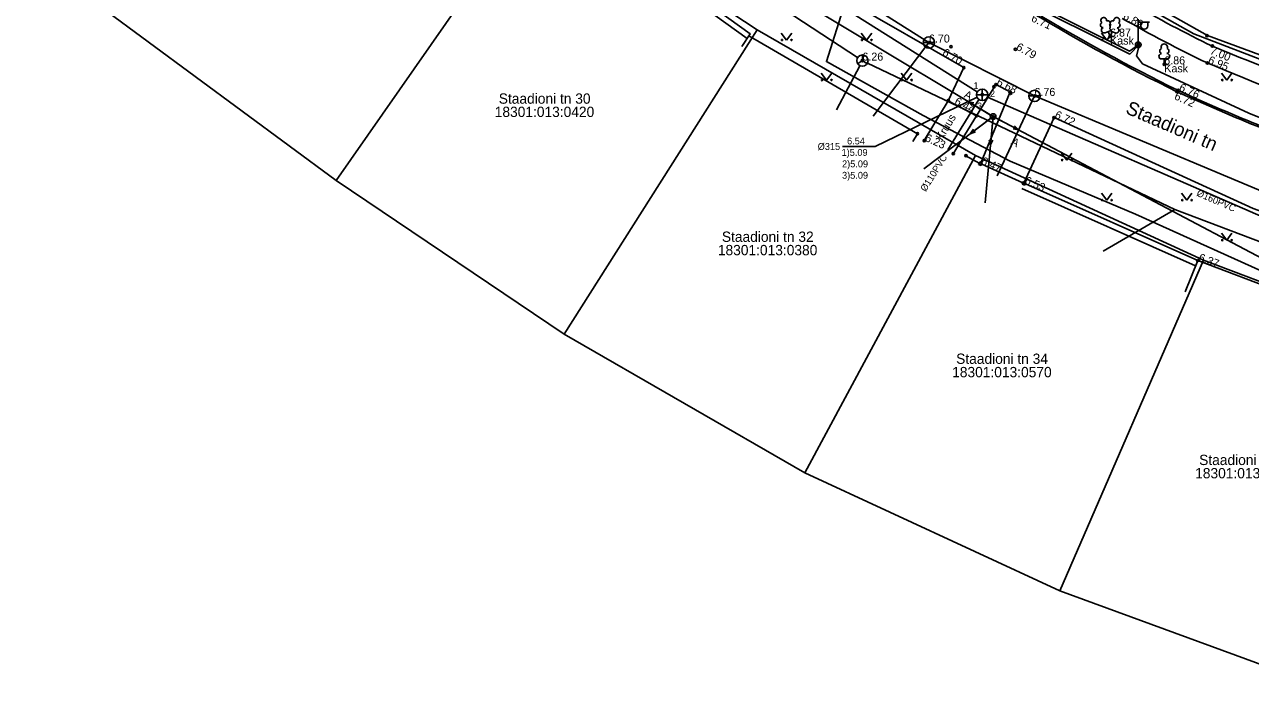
# Model space of a CAD drawing. Extents: x 473307 to 473719, y 6532843 to 6533381.
# Drawn here: x 473476.8 to 473584, y 6532884.7 to 6532942.8 of the extents above; entities that cross this region are included whole.
import ezdxf

# ---------------------------------------------------------------- set-up
doc = ezdxf.new("R2010")
doc.units = 0
for name, color, linetype in [('AED', 7, 'Continuous'), ('Default', 7, 'Continuous'), ('HALJASTUS', 7, 'Continuous'), ('KKAEV', 7, 'Continuous'), ('KKAEV_NR', 7, 'Continuous'), ('KORGUS', 7, 'Continuous'), ('KPKAABEL', 7, 'Continuous'), ('KTRASS', 7, 'Continuous'), ('KTRASS_TEKST', 7, 'Continuous'), ('MPKAABEL', 7, 'Continuous'), ('MPOHULIIN', 7, 'Continuous'), ('PIIR', 7, 'Continuous'), ('POST', 7, 'Continuous'), ('PUU', 7, 'Continuous'), ('SIKAEV', 7, 'Continuous'), ('SITRASS', 7, 'Continuous'), ('TEE', 7, 'Continuous'), ('VKAEV', 7, 'Continuous'), ('VTRASS', 7, 'Continuous')]:
    doc.layers.add(name, color=color, linetype=linetype)

# ---------------------------------------------------------------- blocks, each defined once
blk = doc.blocks.new('KAKAEV')
at = {"layer": 'Default'}
for p, q in [((-1, 0), (1, 0)), ((0, -1), (0, 1))]:
    blk.add_line(p, q, dxfattribs=at)
blk.add_circle((0, 0), 1, dxfattribs=at)
blk = doc.blocks.new('SIKAEV')
at = {"layer": 'Default'}
for p, q in [((0, 0), (-0.83, -0.55)), ((0, 1), (0, 0)), ((0, 0), (0.83, -0.55))]:
    blk.add_line(p, q, dxfattribs=at)
blk.add_circle((0, 0), 1, dxfattribs=at)
blk = doc.blocks.new('PUPOST')
at = {"layer": 'Default'}
blk.add_circle((0, 0), 0.5, dxfattribs=at)
blk = doc.blocks.new('VEKAEV')
at = {"layer": 'Default'}
blk.add_line((-1, 0), (1, 0), dxfattribs=at)
blk.add_circle((0, 0), 1, dxfattribs=at)
blk = doc.blocks.new('VARPOS')
at = {"layer": 'Default'}
for p, q in [((-0.25, 0.25), (-0.25, -0.25)), ((-0.25, 0.25), (0.25, 0.25)), ((0.25, 0.25), (0.25, -0.25)), ((-0.25, -0.25), (0.25, -0.25))]:
    blk.add_line(p, q, dxfattribs=at)
blk = doc.blocks.new('LEHTP1')
at = {"layer": 'Default'}
for p, q in [((0.48, 0.95), (-0.48, 0.95)), ((0, 0), (0, 0.95)), ((0.76, 0), (0, 0))]:
    blk.add_line(p, q, dxfattribs=at)
for centre, radius, start, end in [((-0.34, 2.35), 0.465, 109.0217, 253.1415), ((0, 3.04), 0.554, 332.5799, 207.4201), ((0.34, 2.35), 0.465, 286.8508, 70.9859), ((-0.47, 1.42), 0.475, 90.0016, 269.3953), ((0.47, 1.42), 0.475, 270.6047, 89.9984)]:
    blk.add_arc(centre, radius, start, end, dxfattribs=at)
blk = doc.blocks.new('MEPOST')
at = {"layer": 'Default'}
blk.add_circle((0, 0), 0.5, dxfattribs=at)
for start, end in [(0, 180), (180, 0)]:
    blk.add_arc((0, 0), 0.25, start, end, dxfattribs=at)
blk = doc.blocks.new('VAPOST')
at = {"layer": 'Default'}
for p, q in [((0, 0.5), (0, 4.5)), ((0, 4), (2, 4)), ((0.45, 3.36), (0.45, 4)), ((1.68, 3.36), (1.68, 4))]:
    blk.add_line(p, q, dxfattribs=at)
blk.add_arc((1.07, 3.36), 0.613, 180, 0, dxfattribs=at)
blk = doc.blocks.new('LEHTP2')
at = {"layer": 'Default'}
for p, q in [((-0.88, 0.67), (0.01, 1.02)), ((0, 0), (-0.35, 0.88)), ((0, 0), (0.36, 0.88)), ((0.76, 0), (0, 0)), ((0.01, 1.02), (0.89, 0.66))]:
    blk.add_line(p, q, dxfattribs=at)
blk.add_lwpolyline([(0.01, 2.01), (-0.03, 1.86), (-0.03, 1.82), (-0.01, 1.76), (0.03, 1.69), (0.04, 1.65), (0.01, 1.58), (-0.04, 1.48), (-0.05, 1.43), (-0.04, 1.4), (-0.02, 1.34), (0.05, 1.22), (0.06, 1.18), (0.05, 1.14), (0.02, 1.07), (0.01, 1.02)], dxfattribs=at)
for centre, radius, start, end in [((-1.26, 2.01), 0.448, 111.4304, 274.4987), ((-1.11, 2.83), 0.512, 111.5027, 232.5173), ((-1.11, 2.83), 0.512, 350.4856, 111.5002), ((-0.44, 2.33), 0.448, 308.5041, 111.5725), ((0.48, 2.32), 0.45, 67.7016, 230.5126), ((1.16, 2.81), 0.512, 67.6168, 188.6314), ((1.29, 1.99), 0.448, 264.6183, 67.6866), ((1.16, 2.81), 0.512, 306.5997, 67.6143), ((-1.05, 1.12), 0.475, 111.5014, 291.5004), ((0.01, 1.53), 0.475, 66.7655, 111.5015), ((1.07, 1.1), 0.475, 247.6166, 67.6155)]:
    blk.add_arc(centre, radius, start, end, dxfattribs=at)
blk = doc.blocks.new('MPSUUN')
at = {"layer": 'Default'}
for p, q in [((0.5, 0), (5, 0)), ((5, 0), (4.1, 0.3)), ((5, 0), (4.1, -0.3))]:
    blk.add_line(p, q, dxfattribs=at)
blk = doc.blocks.new('MURU')
at = {"layer": 'Default'}
for p, q in [((-0.93, 1.21), (0, 0)), ((0, 0), (0.89, 1.21))]:
    blk.add_line(p, q, dxfattribs=at)
for centre in [(-0.8, 0), (0.86, 0)]:
    blk.add_circle(centre, 0.11, dxfattribs=at)

msp = doc.modelspace()

# ---------------------------------------------------------------- linework, layer by layer
at = {"layer": 'AED'}
for points in [[(473550.05, 6532959.21), (473554.17, 6532956.45), (473573.72, 6532945.51), (473580.25, 6532941.8), (473591.86, 6532937.52), (473605.92, 6532932.3), (473608.29, 6532931.42), (473621.23, 6532928.23), (473637.54, 6532925.08), (473652.53, 6532925.14), (473654.3, 6532926.84), (473651.93, 6532941.68), (473648.98, 6532959.55), (473630.65, 6532956.49)], [(473528.46, 6532950.46), (473540.26, 6532941.94), (473539.54, 6532940.84)], [(473559.12, 6532931.28), (473560.28, 6532930.64)], [(473560.51, 6532930.53), (473564.09, 6532928.92)], [(473564.32, 6532928.82), (473579.4, 6532922.12)], [(473596.07, 6532915.79), (473579.4, 6532922.12), (473578.3, 6532919.39)]]:
    msp.add_lwpolyline(points, dxfattribs=at)
at = {"layer": 'HALJASTUS'}
for points in [[(473528.06, 6532950.13), (473539.99, 6532941.52)], [(473540.15, 6532941.77), (473554.89, 6532933.2), (473554.49, 6532932.53)], [(473564, 6532928.41), (473579.2, 6532921.66)]]:
    msp.add_lwpolyline(points, dxfattribs=at)
at = {"layer": 'KKAEV_NR'}
msp.add_lwpolyline([(473560.1, 6532936.39), (473551.19, 6532932.09), (473548.34, 6532932.09)], dxfattribs=at)
at = {"layer": 'KORGUS'}
for centre in [(473555.89, 6532941.18), (473571.73, 6532941.7), (473580.2, 6532941.77), (473557.82, 6532940.82), (473557.82, 6532940.82), (473563.45, 6532940.59), (473563.45, 6532940.59), (473580.68, 6532940.87), (473550.07, 6532939.6), (473550.07, 6532939.6), (473558.94, 6532938.99), (473576.47, 6532939.27), (473580.24, 6532939.4), (473560.55, 6532936.61), (473560.55, 6532936.61), (473560.55, 6532936.61), (473560.55, 6532936.61), (473561.58, 6532937.32), (473561.58, 6532937.32), (473561.74, 6532937.5), (473562.98, 6532936.86), (473563.03, 6532936.73), (473577.58, 6532936.88), (473577.7, 6532937.01), (473557.58, 6532936.09), (473565.12, 6532936.51), (473560.06, 6532934.77), (473561.5, 6532934.71), (473566.83, 6532934.62), (473554.89, 6532933.2), (473555.48, 6532932.6), (473558.02, 6532931.46), (473559.12, 6532931.28), (473560.39, 6532930.58), (473564.2, 6532928.87), (473579.4, 6532922.12)]:
    msp.add_circle(centre, 0.1, dxfattribs=at)
at = {"layer": 'KPKAABEL'}
msp.add_lwpolyline([(473552.43, 6532965.74), (473552.25, 6532955.74), (473551.4, 6532952.25), (473548.54, 6532944.6), (473546.92, 6532939.52), (473555.37, 6532934.8), (473562.98, 6532930.8), (473573.94, 6532926.16), (473585, 6532921.18), (473597.71, 6532916.33), (473608.1, 6532913.36), (473620.13, 6532910.12), (473635.44, 6532908.14), (473647.32, 6532907.13), (473658.18, 6532907.68), (473669.9, 6532907.95), (473678.24, 6532908.17), (473679.84, 6532908.72), (473681.3, 6532908.76), (473682.62, 6532907.44), (473683.14, 6532903.8)], dxfattribs=at)
at = {"layer": 'KTRASS'}
for p, q in [((473505.34, 6532971.33), (473560.12, 6532936.88)), ((473557.55, 6532931.79), (473560.26, 6532936.2)), ((473561.01, 6532936.41), (473600.98, 6532918.97))]:
    msp.add_line(p, q, dxfattribs=at)
at = {"layer": 'MPKAABEL'}
for points in [[(473592.16, 6532931.66), (473583.87, 6532934.99), (473574.57, 6532939.31), (473574.03, 6532940.03), (473574.3, 6532941.03), (473573.47, 6532940.17), (473563.47, 6532945.17), (473556.13, 6532949.37), (473546.42, 6532955.03), (473536.14, 6532961.46), (473535.98, 6532962.87), (473534.66, 6532962.57), (473525.66, 6532968.57), (473517.1, 6532975.07), (473509.15, 6532981.52), (473503.05, 6532987.78), (473502.69, 6532988.63), (473501.29, 6532988.87), (473494.53, 6532995.72), (473488.46, 6533001.87), (473481.1, 6533010.08), (473475.3, 6533017.48)], [(473535.98, 6532962.87), (473536.14, 6532961.46), (473546.42, 6532955.03), (473556.13, 6532949.37), (473563.47, 6532945.17), (473573.47, 6532940.17), (473574.3, 6532941.03)], [(473574.3, 6532941.03), (473573.43, 6532940.43), (473563.57, 6532945.36), (473556.23, 6532949.55)], [(473574.3, 6532941.03), (473574.03, 6532940.03), (473574.57, 6532939.31), (473583.87, 6532934.99), (473592.16, 6532931.66), (473601.04, 6532928.37), (473611.16, 6532925.49), (473612.18, 6532926.23)]]:
    msp.add_lwpolyline(points, dxfattribs=at)
at = {"layer": 'MPOHULIIN'}
for points in [[(473423.19, 6533272.9), (473391.79, 6533270.48), (473361.09, 6533267.92), (473364.23, 6533220.93), (473380.48, 6533175.32), (473396.17, 6533131.76), (473413.57, 6533083.53), (473430.97, 6533052.6), (473459.84, 6533016.94), (473493.25, 6532975.71), (473524.16, 6532957.13), (473561.5, 6532934.71), (473599.71, 6532914.54), (473648.18, 6532910.18)], [(473561.5, 6532934.71), (473555.43, 6532930.15)], [(473561.5, 6532934.71), (473560.82, 6532927.15)]]:
    msp.add_lwpolyline(points, dxfattribs=at)
at = {"layer": 'PIIR'}
for points in [[(473486.57, 6533007.64), (473478.82, 6533017), (473548.5, 6533028.91), (473572.63, 6533056.43), (473618.6, 6533063.82), (473630.89, 6533065.72), (473654.16, 6532926.37), (473652.82, 6532924.82), (473637.7, 6532924.6), (473625.07, 6532926.73), (473607.63, 6532930.98), (473579.04, 6532941.93), (473554.34, 6532955.84), (473531.51, 6532970.21), (473509.62, 6532987.09)], [(473501.05, 6532969.5), (473521.95, 6532954.78), (473504.05, 6532929.11), (473479.39, 6532947.34)], [(473521.95, 6532954.78), (473540.88, 6532942.28), (473523.99, 6532915.67), (473504.05, 6532929.11)], [(473540.88, 6532942.28), (473559.95, 6532931.3), (473545.03, 6532903.55), (473523.99, 6532915.67)], [(473559.95, 6532931.3), (473579.89, 6532922.16), (473567.33, 6532893.22), (473545.03, 6532903.55)], [(473590.66, 6532884.69), (473567.33, 6532893.22), (473579.89, 6532922.16), (473600.1, 6532914.5)]]:
    msp.add_lwpolyline(points, close=True, dxfattribs=at)
msp.add_lwpolyline([(473455.33, 6533045.76), (473478.82, 6533017), (473486.57, 6533007.64), (473509.62, 6532987.09), (473531.51, 6532970.21), (473554.34, 6532955.84), (473579.04, 6532941.93), (473607.63, 6532930.98), (473625.07, 6532926.73), (473637.7, 6532924.6), (473652.82, 6532924.82), (473654.16, 6532926.37), (473664.64, 6532927.81), (473668.24, 6532906.4), (473641.69, 6532906.33), (473620.6, 6532909.02), (473600.1, 6532914.5), (473579.89, 6532922.16), (473559.95, 6532931.3), (473540.88, 6532942.28), (473521.95, 6532954.78), (473501.05, 6532969.5), (473492.55, 6532977.62), (473473.12, 6532997.79)], dxfattribs=at)
at = {"layer": 'SITRASS'}
msp.add_line((473547.81, 6532935.29), (473549.84, 6532939.15), dxfattribs=at)
for points in [[(473494.73, 6532977.14), (473516.49, 6532961.58), (473549.65, 6532939.87)], [(473550.52, 6532939.38), (473577.39, 6532926.59), (473593.85, 6532920.34), (473606.28, 6532915.93), (473618.38, 6532912.49)], [(473571.13, 6532922.94), (473577.39, 6532926.59)]]:
    msp.add_lwpolyline(points, dxfattribs=at)
at = {"layer": 'TEE'}
for points in [[(473507.27, 6532973.24), (473516.73, 6532966.21), (473521.98, 6532962.13), (473526.06, 6532959.02), (473526.41, 6532958.66), (473523.97, 6532954.44), (473525.69, 6532952.96), (473528.95, 6532956.69), (473529.58, 6532956.85), (473534.19, 6532954.06), (473548.77, 6532944.84), (473558.94, 6532938.99), (473557.58, 6532936.09)], [(473560.39, 6532930.58), (473562.98, 6532936.86), (473561.74, 6532937.5), (473560.06, 6532934.77)], [(473557.58, 6532936.09), (473555.48, 6532932.6)], [(473560.06, 6532934.77), (473557.58, 6532936.09)], [(473560.06, 6532934.77), (473558.02, 6532931.46)], [(473596.29, 6532916.12), (473598.15, 6532921.75), (473584.24, 6532926.66), (473566.83, 6532934.62), (473564.2, 6532928.87)]]:
    msp.add_lwpolyline(points, dxfattribs=at)
for centre, radius, start, end in [((473627.25, 6533037.15), 106.96, 239.9365, 244.1887), ((473649.99, 6533084.53), 164.45, 238.9084, 243.8764), ((473649.99, 6533084.53), 164.3, 238.9079, 243.8758), ((473627.8, 6533039.27), 110.62, 240.1854, 244.5365), ((473662.37, 6533136.34), 211.86, 247.3206, 250.935), ((473643.9, 6533087.77), 161.45, 246.7751, 251.5335), ((473641.39, 6533075.27), 152.39, 245.2447, 248.3026), ((473641.39, 6533075.27), 152.24, 245.2454, 248.3031)]:
    msp.add_arc(centre, radius, start, end, dxfattribs=at)
at = {"layer": 'VTRASS'}
for points in [[(473503.73, 6532976.93), (473535.26, 6532954.21), (473555.89, 6532941.18), (473565.12, 6532936.51), (473600.67, 6532921.59), (473636.51, 6532914.62), (473674.92, 6532915.36), (473675.56, 6532915.43)], [(473551.01, 6532934.73), (473555.89, 6532941.18)], [(473561.86, 6532929.52), (473565.12, 6532936.51)]]:
    msp.add_lwpolyline(points, dxfattribs=at)

# ---------------------------------------------------------------- block references
at = {"layer": 'AED'}
for p, xscale, yscale, rotation in [((473560.39, 6532930.58), 0.4999999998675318, 0.4999999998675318, -23.82899570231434), ((473564.2, 6532928.87), 0.49999999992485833, 0.49999999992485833, 155.39560992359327)]:
    msp.add_blockref('VARPOS', p, dxfattribs=dict(at, xscale=xscale, yscale=yscale, rotation=rotation))
at = {"layer": 'HALJASTUS', "xscale": 0.5, "yscale": 0.5}
for p in [(473543.44, 6532941.4), (473550.44, 6532941.4), (473571.44, 6532941.4), (473546.94, 6532937.9), (473553.94, 6532937.9), (473581.94, 6532937.9), (473567.94, 6532930.9), (473571.44, 6532927.4), (473578.44, 6532927.4), (473581.94, 6532923.9)]:
    msp.add_blockref('MURU', p, dxfattribs=at)
at = {"layer": 'KKAEV', "xscale": 0.5, "yscale": 0.5}
msp.add_blockref('KAKAEV', (473560.55, 6532936.61), dxfattribs=at)
at = {"layer": 'MPOHULIIN'}
for xscale, yscale, rotation in [(0.49999999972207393, 0.49999999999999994, 149.02202911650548), (0.4999999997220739, 0.5000000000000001, -143.03393283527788), (0.4999999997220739, 0.5000000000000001, -27.8325341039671), (0.499999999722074, 0.5, -95.15544159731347)]:
    msp.add_blockref('MPSUUN', (473561.5, 6532934.71), dxfattribs=dict(at, xscale=xscale, yscale=yscale, rotation=rotation))
at = {"layer": 'POST', "xscale": 0.5, "yscale": 0.5}
for name, p in [('VAPOST', (473574.19, 6532940.97)), ('MEPOST', (473574.19, 6532940.97)), ('PUPOST', (473561.5, 6532934.71))]:
    msp.add_blockref(name, p, dxfattribs=at)
at = {"layer": 'PUU', "xscale": 0.5, "yscale": 0.5}
for name, p in [('LEHTP2', (473571.73, 6532941.7)), ('LEHTP1', (473576.47, 6532939.27))]:
    msp.add_blockref(name, p, dxfattribs=at)
at = {"layer": 'SIKAEV', "xscale": 0.5, "yscale": 0.5}
msp.add_blockref('SIKAEV', (473550.07, 6532939.6), dxfattribs=at)
at = {"layer": 'VKAEV', "xscale": 0.5, "yscale": 0.5}
for p in [(473555.89, 6532941.18), (473565.12, 6532936.51)]:
    msp.add_blockref('VEKAEV', p, dxfattribs=at)

# ---------------------------------------------------------------- texts
at = {"layer": 'KKAEV_NR'}
for s, p in [('1', (473559.78, 6532937.11)), ('2', (473561.22, 6532936.41)), ('3', (473560.09, 6532935.33)), ('6.54', (473548.73, 6532932.27)), ('%%c315', (473546.16, 6532931.79)), ('1)5.09', (473548.25, 6532931.27)), ('2)5.09', (473548.29, 6532930.27)), ('3)5.09', (473548.29, 6532929.27))]:
    msp.add_text(s, height=0.6, dxfattribs=at).set_placement(p)
at = {"layer": 'KORGUS'}
for s, rotation, p in [('6.71', 335.0102, (473564.77, 6532943.07)), ('6.89', 330.7726, (473572.8, 6532943.29)), ('6.87', 0.04, (473571.73, 6532941.7)), ('6.79', 331.1687, (473563.45, 6532940.59)), ('6.70', 330.0897, (473557, 6532940.11)), ('6.86', 0.04, (473576.47, 6532939.27)), ('6.95', 337.1525, (473580.24, 6532939.4)), ('7.00', 337.5504, (473580.41, 6532940.22)), ('6.68', 332.6502, (473561.74, 6532937.5)), ('6.76', 0.04, (473565.12, 6532936.51)), ('6.72', 335.6005, (473577.29, 6532936.25)), ('6.76', 335.6005, (473577.7, 6532937.01)), ('6.44', 331.9048, (473558.06, 6532935.83)), ('6.72', 335.3819, (473566.83, 6532934.62)), ('6.23', 335.6598, (473555.48, 6532932.6)), ('6.47', 335.8304, (473560.39, 6532930.58)), ('6.53', 335.9164, (473564.2, 6532928.87)), ('6.37', 339.2152, (473579.4, 6532922.12))]:
    msp.add_text(s, height=0.7, rotation=rotation, dxfattribs=at).set_placement(p)
for s, p in [('6.70', (473555.89, 6532941.18)), ('6.26', (473550.07, 6532939.6))]:
    msp.add_text(s, height=0.7, dxfattribs=at).set_placement(p)
at = {"layer": 'KTRASS_TEKST'}
for s, rotation, p in [('%%c110PVC', 57.9484, (473555.6, 6532928.09)), ('%%c160PVC', 336.4336, (473579.24, 6532927.8))]:
    msp.add_text(s, height=0.6, rotation=rotation, dxfattribs=at).set_placement(p)
at = {"layer": 'PIIR'}
for s, p in [('Staadioni tn 30', (473518.27, 6532935.83)), ('18301:013:0420', (473517.92, 6532934.67)), ('Staadioni tn 32', (473537.78, 6532923.75)), ('18301:013:0380', (473537.43, 6532922.58)), ('Staadioni tn 34', (473558.27, 6532913.08)), ('18301:013:0570', (473557.92, 6532911.91)), ('Staadioni tn 36', (473579.52, 6532904.23)), ('18301:013:0290', (473579.17, 6532903.07))]:
    msp.add_text(s, height=0.9, dxfattribs=at).set_placement(p)
at = {"layer": 'PUU'}
for p in [(473571.73, 6532941), (473576.47, 6532938.57)]:
    msp.add_text('Kask', height=0.7, dxfattribs=at).set_placement(p)
at = {"layer": 'TEE'}
for s, height, rotation, p in [('A', 0.7, 334.4091, (473558.89, 6532936.41)), ('Staadioni tn', 1.2, 336.6711, (473573.01, 6532935.02)), ('Kruus', 0.7, 59.3187, (473557.04, 6532932.56)), ('A', 0.7, 330.8448, (473563, 6532932.31))]:
    msp.add_text(s, height=height, rotation=rotation, dxfattribs=at).set_placement(p)

doc.saveas('drawing.dxf')
